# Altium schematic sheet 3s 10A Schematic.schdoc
size 272 x 214 mm
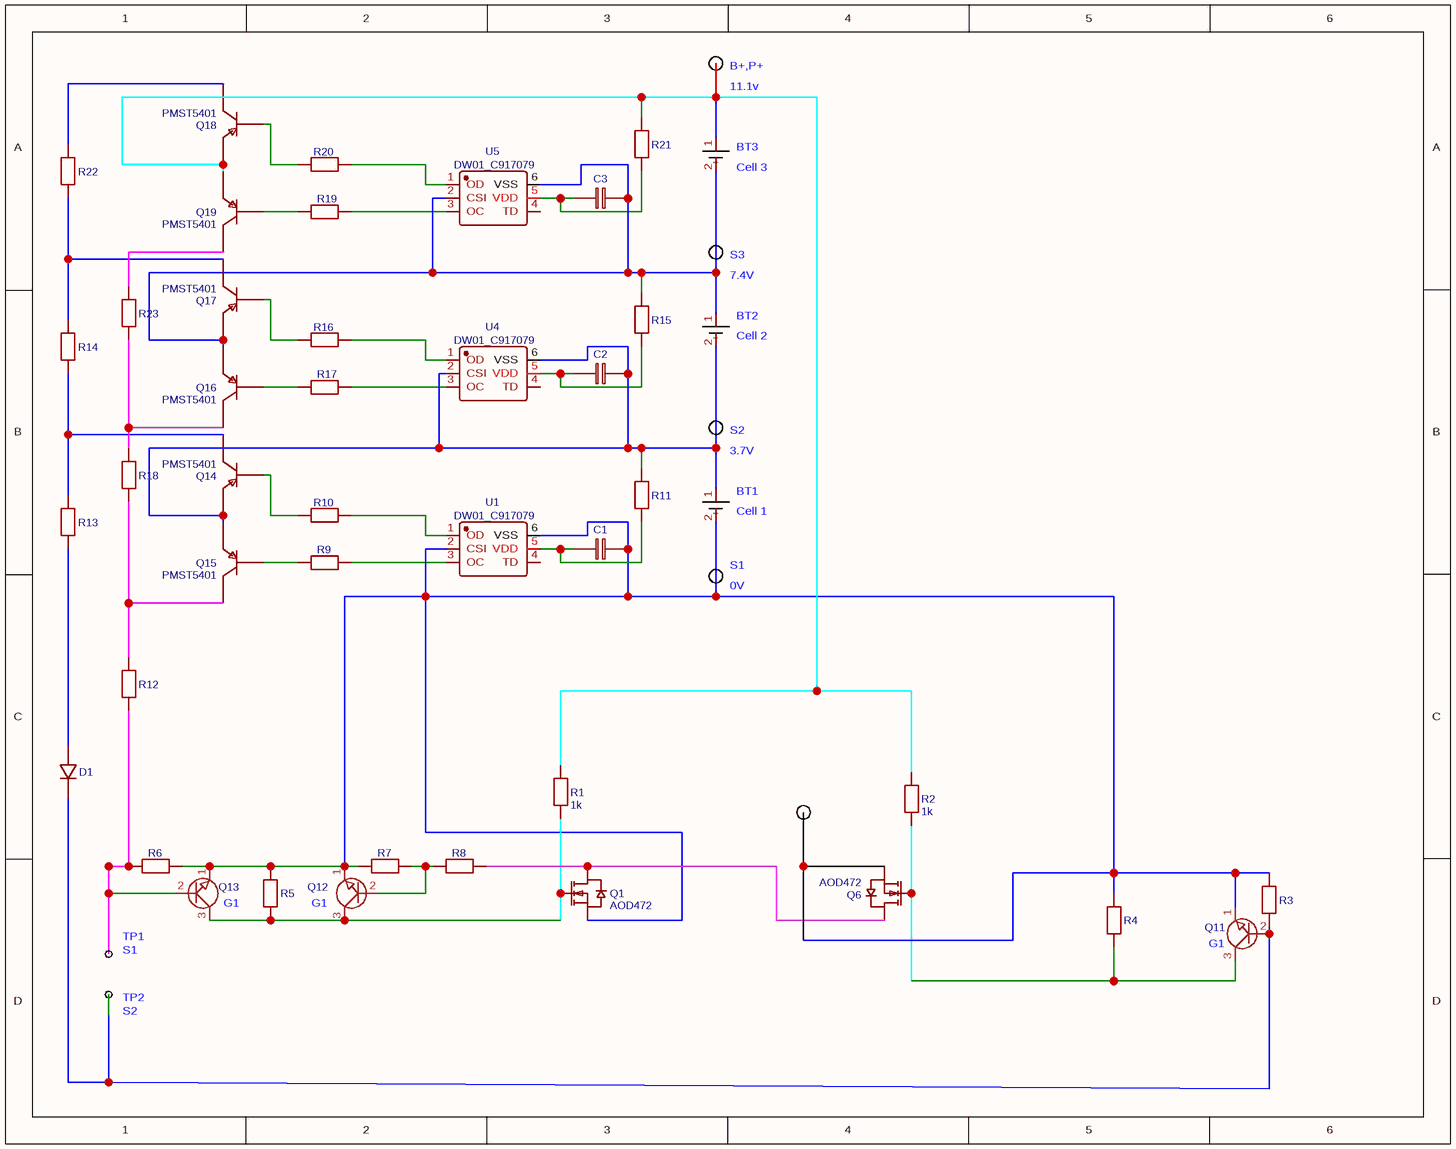
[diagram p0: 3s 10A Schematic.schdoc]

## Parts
C1  0.1u  [C0603]  (value not drawn)
C2  0.1u  [C0603]  (value not drawn)
C3  0.1u  [C0603]  (value not drawn)
D1  1N4007W  [SOD-123_L2.8-W1.8-LS3.7-RD]  (value not drawn)
Q1  AOD472  [TO-252-2_L6.6-W6.1-P4.57-LS9.9-BR-CW]
Q6  AOD472  [TO-252-2_L6.6-W6.1-P4.57-LS9.9-BR-CW]
Q11  2N2222  [NPN]  (value not drawn)
Q12  2N2222  [NPN]  (value not drawn)
Q13  2N2222  [NPN]  (value not drawn)
Q14  PMST5401  [SOT323]
Q15  PMST5401  [SOT323]
Q16  PMST5401  [SOT323]
Q17  PMST5401  [SOT323]
Q18  PMST5401  [SOT323]
Q19  PMST5401  [SOT323]
R1  1k  [R0603]
R2  1k  [R0603]
R3  1k  [R0603]  (value not drawn)
R4  1k  [R0603]  (value not drawn)
R5  1k  [R0603]  (value not drawn)
R6  1k  [R0603]  (value not drawn)
R7  1k  [R0603]  (value not drawn)
R8  1k  [R0603]  (value not drawn)
R9  1k  [R0603]  (value not drawn)
R10  1k  [R0603]  (value not drawn)
R11  1k  [R0603]  (value not drawn)
R12  1k  [R0603]  (value not drawn)
R13  1k  [R0603]  (value not drawn)
R14  1k  [R0603]  (value not drawn)
R15  1k  [R0603]  (value not drawn)
R16  1k  [R0603]  (value not drawn)
R17  1k  [R0603]  (value not drawn)
R18  1k  [R0603]  (value not drawn)
R19  1k  [R0603]  (value not drawn)
R20  1k  [R0603]  (value not drawn)
R21  1k  [R0603]  (value not drawn)
R22  1k  [R0603]  (value not drawn)
R23  1k  [R0603]  (value not drawn)
U1  DW01_C917079  [SOT-23-6_L2.9-W1.6-P0.95-LS2.8-BL]
U2  Li-ion battery  [LI-ION BATTERY]  (value not drawn)
U3  Li-ion battery  [LI-ION BATTERY]  (value not drawn)
U4  DW01_C917079  [SOT-23-6_L2.9-W1.6-P0.95-LS2.8-BL]
U5  DW01_C917079  [SOT-23-6_L2.9-W1.6-P0.95-LS2.8-BL]
U6  Li-ion battery  [LI-ION BATTERY]  (value not drawn)

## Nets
NetC1_1: C1.1 R11.1 U1.5(VDD)
NetC1_2: C1.2 Q1.3(S) Q6.3(S) Q11.1(E) Q12.1(E) Q13.1(E) R3.2 R4.2 R5.2 R6.1 R7.2 U1.2(CSI) U1.6(VSS) U2.2(-)
NetC2_1: C2.1 R15.1 U4.5(VDD)
NetC2_2: C2.2 Q14.2(E) Q15.2(E) R11.2 U2.1(+) U3.2(-) U4.2(CSI) U4.6(VSS)
NetC3_1: C3.1 R21.1 U5.5(VDD)
NetC3_2: C3.2 Q16.2(E) Q17.2(E) R15.2 U3.1(+) U5.2(CSI) U5.6(VSS) U6.2(-)
NetD1_1: D1.1 Q11.2(B) R3.1
NetD1_2: D1.2 R13.1
NetQ1_1: Q1.1(G) Q12.3(C) Q13.3(C) R1.1 R5.1
NetQ1_2: Q1.2(D) Q6.2(D) R8.1
NetQ6_1: Q6.1(G) Q11.3(C) R2.1 R4.1
NetQ12_2: Q12.2(B) R7.1 R8.2
NetQ13_2: Q13.2(B) R6.2 R12.1
NetQ14_1: Q14.1(B) R10.1
NetQ14_3: Q14.3(C) R13.2 R14.1
NetQ15_1: Q15.1(B) R9.1
NetQ15_3: Q15.3(C) R12.2 R18.1
NetQ16_1: Q16.1(B) R17.1
NetQ16_3: Q16.3(C) R18.2 R23.1
NetQ17_1: Q17.1(B) R16.1
NetQ17_3: Q17.3(C) R14.2 R22.1
NetQ18_1: Q18.1(B) R20.1
NetQ18_2: Q18.2(E) Q19.2(E) R1.2 R2.2 R21.2 U6.1(+)
NetQ18_3: Q18.3(C) R22.2
NetQ19_1: Q19.1(B) R19.1
NetQ19_3: Q19.3(C) R23.2
NetR9_2: R9.2 U1.3(OC)
NetR10_2: R10.2 U1.1(OD)
NetR16_2: R16.2 U4.1(OD)
NetR17_2: R17.2 U4.3(OC)
NetR19_2: R19.2 U5.3(OC)
NetR20_2: R20.2 U5.1(OD)

Not connected (* = marked no-connect by the designer): U1 4(TD); U4 4(TD); U5 4(TD)

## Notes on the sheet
- B+,P+
- 11.1v
- (near U6) BT3
- (near U6) Cell 3
- S3
- (near U3) 7.4V
- (near U3) BT2
- (near U3) Cell 2
- S2
- (near U2) 3.7V
- (near U2) BT1
- (near U2) Cell 1
- (near U2) S1
- 0V
- TP1
- S1
- (near Q13) G1
- (near Q12) G1
- (near Q11) G1
- TP2

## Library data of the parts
C1-C3 = 0.1u: nameAlias: Value(F); Contributor: LCEDA_Lib
D1 = 1N4007W: BOM_Manufacturer: BLUE ROCKET; Contributor: LCEDA_Lib
Q1 Q6 = AOD472: BOM_Manufacturer: VBsemi Elec; Contributor: LCSC
Q11-Q13 = 2N2222: Contributor: KiCad
Q14-Q19 = PMST5401: description: PNP High-voltage Transistor
R1-R23 = 1k: nameAlias: Value(Ω); Contributor: LCEDA_Lib
U1 U4 U5 = DW01_C917079: BOM_Manufacturer: JSMSEMI(杰盛微); BOM_Manufacturer Part: DW01; Contributor: LCSC
U2 U3 U6 = Li-ion battery: Contributor: Mega Videolar (H. Selim Serdar)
